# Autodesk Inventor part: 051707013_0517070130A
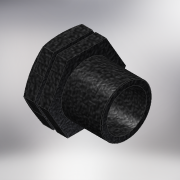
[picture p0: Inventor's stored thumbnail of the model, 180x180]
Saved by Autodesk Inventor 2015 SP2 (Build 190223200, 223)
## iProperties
Created: 2017-05
Part Number: 051707013_0517070130A
Material: Generic
Description: PLASSON PLUG 1.1/4"
Document SubType Name: Modeling
Designer: Кирилл
Density: 1 g/cm^3
Appearance: Black Cast
Author: Кирилл
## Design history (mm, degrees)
derived "051707.ipt"
feature "Solid1::051707.ipt"
tag "TaggingFeature1"
body "Solid1"
other parameters: "d1" = 41.91, "d2" = 46, "d3" = 32, "d5" = 21, "d6" = 5.42857, "d8" = 0.38, "d12" = 0, "d14" = 1.80952, "d15" = 38, "d16" = 2.17143, "d17" = 5.42857, "d19" = 0, "d21" = 2.86, "d29" = 0, "H_" = 38, "R_" = 41.91, "E_" = 46, "l_2" = 21, "d20" = 4.33333
